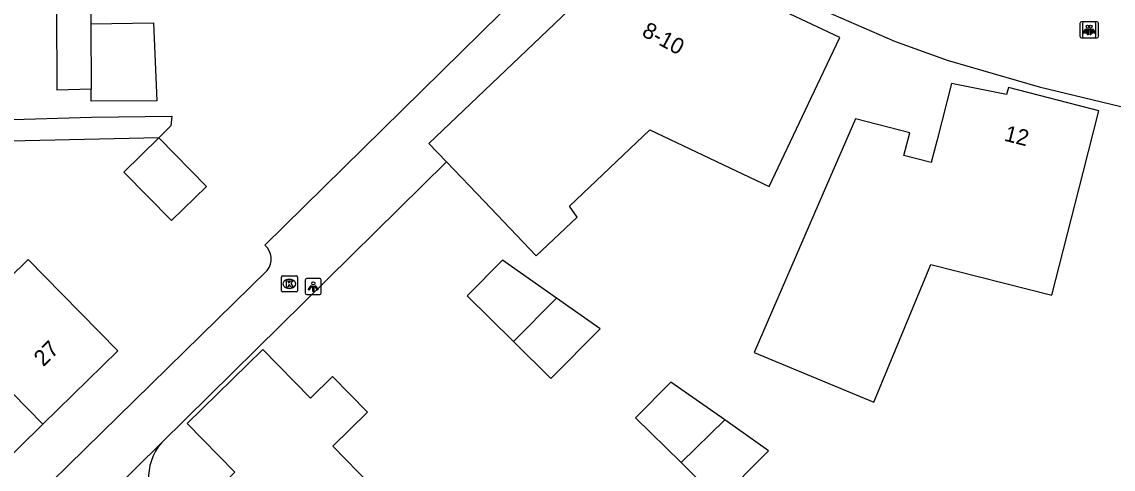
# Model space of a CAD drawing. Extents: x 162880 to 165536, y 384011 to 385179.
# Drawn here: x 164079 to 164147.1, y 384262.9 to 384290.9 of the extents above; entities that cross this region are included whole.
import ezdxf

# ---------------------------------------------------------------- set-up
doc = ezdxf.new("R2010")
doc.units = 0
for name, color, linetype in [('IMGEO_Kolk', 7, 'Continuous'), ('IMGEO_Lichtpunt', 7, 'Continuous'), ('IMGEO_Pand', 7, 'Continuous'), ('IMGEO_Pand_nummerreeks', 7, 'Continuous'), ('IMGEO_Voetpad_open', 7, 'Continuous')]:
    doc.layers.add(name, color=color, linetype=linetype)

msp = doc.modelspace()

# ---------------------------------------------------------------- linework, layer by layer
at = {"layer": 'IMGEO_Kolk'}
for p, q in [((164095.183, 384274.108), (164095.183, 384274.96)), ((164095.258, 384275.034), (164096.11, 384275.034)), ((164096.184, 384274.96), (164096.184, 384274.108)), ((164095.694, 384274.254), (164095.669, 384274.254)), ((164095.671, 384274.814), (164095.696, 384274.814)), ((164096.11, 384274.034), (164095.258, 384274.034))]:
    msp.add_line(p, q, dxfattribs=at)
for points in [[(164095.183, 384274.108), (164095.183, 384274.96)], [(164095.258, 384275.034), (164096.11, 384275.034)], [(164096.184, 384274.96), (164096.184, 384274.108)], [(164095.504, 384274.734), (164095.627, 384274.734), (164095.627, 384274.583), (164095.757, 384274.734), (164095.921, 384274.734), (164095.775, 384274.583), (164095.928, 384274.334), (164095.776, 384274.334), (164095.691, 384274.498), (164095.627, 384274.431), (164095.627, 384274.334), (164095.504, 384274.334), (164095.504, 384274.734)], [(164096.11, 384274.034), (164095.258, 384274.034)]]:
    msp.add_lwpolyline(points, dxfattribs=at)
for centre, start, end in [((164095.26, 384274.958), 91.55205, 178.44795), ((164095.26, 384274.958), 91.55205, 178.44795), ((164096.108, 384274.958), 1.55205, 88.44795), ((164096.108, 384274.958), 1.55205, 88.44795), ((164095.26, 384274.11), 181.55205, 268.44795), ((164095.26, 384274.11), 181.55205, 268.44795), ((164096.108, 384274.11), 271.55205, 358.44795), ((164096.108, 384274.11), 271.55205, 358.44795)]:
    msp.add_arc(centre, 0.0765, start, end, dxfattribs=at)
for centre, major_axis, ratio, start_param, end_param in [((164095.67, 384274.534), (-0.387, 0.002), 0.722429, 4.712389, 7.853982), ((164095.695, 384274.534), (-0.39, 0.002), 0.717154, 1.570796, 4.712389)]:
    msp.add_ellipse(centre, major_axis=major_axis, ratio=ratio, start_param=start_param, end_param=end_param, dxfattribs=at)
at = {"layer": 'IMGEO_Lichtpunt'}
for p, q in [((164145.067, 384290.817), (164145.067, 384290.01)), ((164145.067, 384290.817), (164145.067, 384290.01)), ((164145.969, 384290.912), (164145.161, 384290.912)), ((164145.969, 384290.912), (164145.161, 384290.912)), ((164145.231, 384290.816), (164145.231, 384290.009)), ((164145.231, 384290.816), (164145.231, 384290.009)), ((164146.133, 384290.911), (164145.325, 384290.911)), ((164146.133, 384290.911), (164145.325, 384290.911)), ((164146.063, 384290.01), (164146.063, 384290.817)), ((164146.063, 384290.01), (164146.063, 384290.817)), ((164146.227, 384290.009), (164146.227, 384290.816)), ((164146.227, 384290.009), (164146.227, 384290.816)), ((164145.161, 384289.916), (164145.969, 384289.916)), ((164145.161, 384289.916), (164145.969, 384289.916)), ((164145.325, 384289.915), (164146.133, 384289.915)), ((164145.325, 384289.915), (164146.133, 384289.915)), ((164097.58, 384274.868), (164096.772, 384274.868)), ((164097.58, 384274.868), (164096.772, 384274.868)), ((164096.678, 384274.773), (164096.678, 384273.966)), ((164096.678, 384274.773), (164096.678, 384273.966)), ((164097.674, 384273.966), (164097.674, 384274.773)), ((164097.674, 384273.966), (164097.674, 384274.773)), ((164096.772, 384273.872), (164097.58, 384273.872)), ((164096.772, 384273.872), (164097.58, 384273.872))]:
    msp.add_line(p, q, dxfattribs=at)
for points in [[(164145.441, 384290.481), (164145.48, 384290.453), (164145.292, 384290.191), (164145.254, 384290.218), (164145.441, 384290.481)], [(164145.605, 384290.48), (164145.644, 384290.452), (164145.456, 384290.19), (164145.418, 384290.217), (164145.605, 384290.48)], [(164145.543, 384290.433), (164145.59, 384290.433), (164145.59, 384290.111), (164145.543, 384290.111), (164145.543, 384290.433)], [(164145.653, 384290.453), (164145.691, 384290.48), (164145.878, 384290.218), (164145.839, 384290.19), (164145.653, 384290.453)], [(164145.707, 384290.432), (164145.754, 384290.432), (164145.754, 384290.11), (164145.707, 384290.11), (164145.707, 384290.432)], [(164145.817, 384290.452), (164145.855, 384290.479), (164146.042, 384290.217), (164146.003, 384290.189), (164145.817, 384290.452)], [(164097.052, 384274.437), (164097.091, 384274.409), (164096.903, 384274.147), (164096.865, 384274.174), (164097.052, 384274.437)], [(164097.154, 384274.389), (164097.201, 384274.389), (164097.201, 384274.067), (164097.154, 384274.067), (164097.154, 384274.389)], [(164097.264, 384274.409), (164097.302, 384274.436), (164097.489, 384274.174), (164097.45, 384274.146), (164097.264, 384274.409)]]:
    msp.add_lwpolyline(points, dxfattribs=at)
for centre in [(164145.566, 384290.615), (164145.73, 384290.614), (164097.177, 384274.571)]:
    msp.add_circle(centre, 0.0994, dxfattribs=at)
for centre, start, end in [((164145.161, 384290.817), 90, 180), ((164145.161, 384290.817), 90, 180), ((164145.325, 384290.816), 90, 180), ((164145.325, 384290.816), 90, 180), ((164145.969, 384290.817), 0, 90), ((164145.969, 384290.817), 0, 90), ((164146.133, 384290.816), 0, 90), ((164146.133, 384290.816), 0, 90), ((164145.161, 384290.01), 180, 270), ((164145.161, 384290.01), 180, 270), ((164145.325, 384290.009), 180, 270), ((164145.325, 384290.009), 180, 270), ((164145.969, 384290.01), 270, 0), ((164145.969, 384290.01), 270, 360), ((164146.133, 384290.009), 270, 0), ((164146.133, 384290.009), 270, 360), ((164096.772, 384274.773), 90, 180), ((164096.772, 384274.773), 90, 180), ((164097.58, 384274.773), 0, 90), ((164097.58, 384274.773), 0, 90), ((164096.772, 384273.966), 180, 270), ((164096.772, 384273.966), 180, 270), ((164097.58, 384273.966), 270, 0), ((164097.58, 384273.966), 270, 360)]:
    msp.add_arc(centre, 0.0946, start, end, dxfattribs=at)
at = {"layer": 'IMGEO_Pand'}
for points in [[(164083.304, 384286.705), (164081.173, 384286.643), (164081.159, 384291.683), (164080.075, 384291.711), (164080.726, 384301.044), (164083.376, 384300.812), (164083.232, 384296.735), (164083.275, 384290.79)], [(164116.191, 384294.568), (164104.396, 384283.315), (164105.502, 384282.156)], [(164105.502, 384282.156), (164107.847, 384279.697), (164111.109, 384276.279), (164113.66, 384278.713), (164113.192, 384279.391), (164118.191, 384284.16), (164125.652, 384280.629), (164127.921, 384285.422), (164128.273, 384286.165), (164130.06, 384289.941), (164122.091, 384293.713), (164121.222, 384291.877), (164116.191, 384294.568)], [(164083.275, 384290.79), (164087.194, 384290.848), (164087.412, 384285.985), (164083.31, 384285.958), (164083.307, 384286.305), (164083.304, 384286.705)], [(164083.275, 384290.79), (164083.304, 384286.705)], [(164145.014, 384280.51), (164145.267, 384281.498), (164146.253, 384285.354), (164140.601, 384286.8), (164140.49, 384286.367), (164137.045, 384287.051), (164136.148, 384283.545), (164135.782, 384282.112), (164134.07, 384282.551), (164134.436, 384283.983), (164131.054, 384284.848), (164129.039, 384280.199), (164124.722, 384270.238), (164132.186, 384267.146), (164135.756, 384275.75), (164143.303, 384273.82), (164145.014, 384280.51)], [(164087.526, 384283.655), (164090.496, 384280.626), (164088.32, 384278.491), (164085.349, 384281.519), (164087.526, 384283.655)], [(164072.57, 384273.616), (164074.874, 384275.876), (164076.98, 384273.729), (164079.356, 384276.061), (164081.46, 384273.916), (164084.962, 384270.347), (164080.28, 384265.756)], [(164112.365, 384273.65), (164109.001, 384276.014), (164106.795, 384273.788), (164109.68, 384270.928)], [(164072.57, 384273.616), (164080.28, 384265.756)], [(164109.68, 384270.928), (164112.017, 384268.612), (164115.103, 384271.725), (164112.365, 384273.65)], [(164109.68, 384270.928), (164112.365, 384273.65)], [(164100.798, 384261.923), (164098.393, 384264.385), (164100.566, 384266.508), (164098.387, 384268.737), (164097.009, 384267.39), (164094.032, 384270.437), (164089.297, 384265.81), (164092.274, 384262.763), (164090.485, 384261.015), (164095.078, 384256.314)], [(164122.878, 384266.034), (164119.518, 384268.395), (164117.312, 384266.169), (164120.148, 384263.358)], [(164122.878, 384266.034), (164120.148, 384263.358)], [(164120.148, 384263.358), (164122.534, 384260.993), (164125.619, 384264.107), (164122.878, 384266.034)], [(164080.28, 384265.756), (164075.737, 384261.302)]]:
    msp.add_lwpolyline(points, dxfattribs=at)
at = {"layer": 'IMGEO_Voetpad_open'}
for points in [[(164094.153, 384276.963), (164113.789, 384296.288), (164115.492, 384298.721)], [(164118.693, 384296.955), (164126.3, 384292.851), (164133.482, 384289.712), (164136.785, 384288.527), (164142.516, 384286.842), (164149.177, 384285.243), (164149.156, 384284.983), (164153.245, 384283.977)], [(164077.211, 384284.78), (164077.726, 384284.794), (164083.317, 384284.95), (164088.338, 384285.009), (164088.288, 384284.403), (164087.526, 384283.655)], [(164087.526, 384283.655), (164064.289, 384283.133), (164062.376, 384281.256)], [(164087.696, 384264.604), (164105.502, 384282.156)], [(164063.201, 384244.93), (164068.383, 384250), (164094.306, 384275.362)], [(164087.696, 384264.604), (164081.379, 384258.358)]]:
    msp.add_lwpolyline(points, dxfattribs=at)
for centre, radius, start, end in [((164093.39, 384276.082), 1.165, 321.82058, 49.09724), ((164090.322, 384262.377), 3.443, 139.7041, 224.34967)]:
    msp.add_arc(centre, radius, start, end, dxfattribs=at)

# ---------------------------------------------------------------- texts
at = {"layer": 'IMGEO_Pand_nummerreeks'}
for s, rotation, p in [('8-10', 331.8584, (164117.64, 384290.073)), ('12', 345.64934, (164140.286, 384283.495)), ('27', 44.43824, (164080.311, 384269.316))]:
    msp.add_text(s, height=1, rotation=rotation, dxfattribs=at).set_placement(p)

doc.saveas('drawing.dxf')
